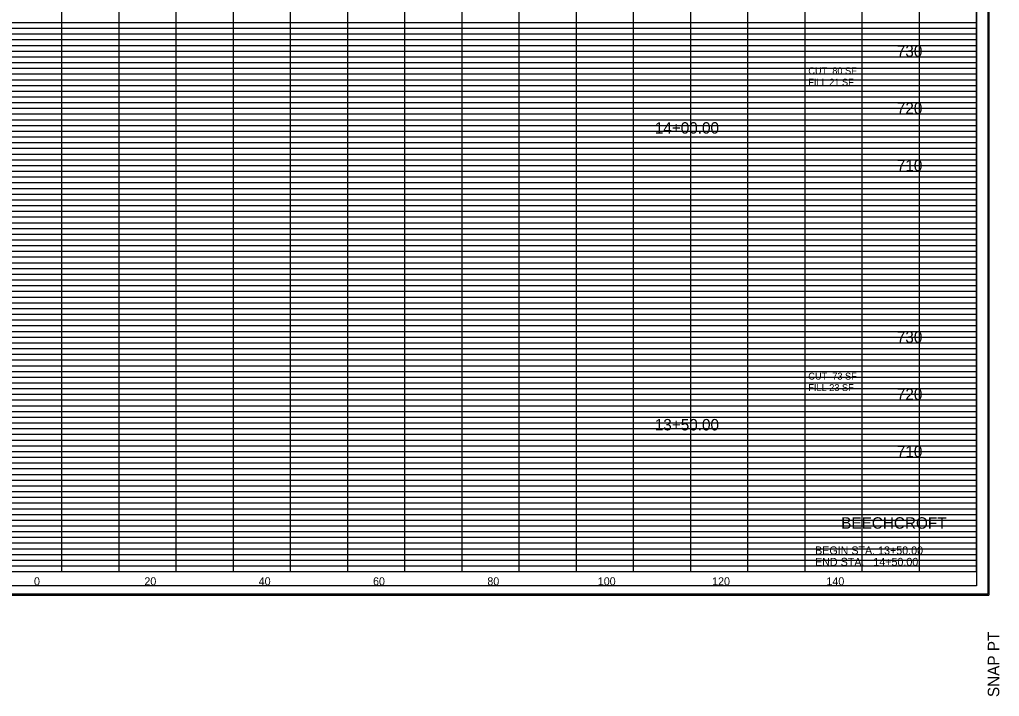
# Model space of a CAD drawing. Extents: x -200 to 1704, y -325 to 2307.
# Drawn here: x 1152.6 to 1324, y 1248.2 to 1366.5 of the extents above; entities that cross this region are included whole.
import ezdxf

# ---------------------------------------------------------------- set-up
doc = ezdxf.new("R2010")
doc.units = 0
for name, color, linetype in [('DESIGN - SHEET - Corner Text', 7, 'Continuous'), ('DESIGN - SHEET - Light Grid', 7, 'Continuous'), ('DESIGN - SHEET - Linework', 7, 'Continuous'), ('DESIGN - SHEET - Plot Shape', 7, 'Continuous'), ('DESIGN - TYPICAL - Text', 7, 'Continuous')]:
    doc.layers.add(name, color=color, linetype=linetype)

msp = doc.modelspace()

# ---------------------------------------------------------------- linework, layer by layer
at = {"layer": 'DESIGN - SHEET - Light Grid'}
for p, q in [((1080, 1366), (1160, 1366)), ((1080, 1365), (1160, 1365)), ((1160, 1366), (1240, 1366)), ((1160, 1365), (1240, 1365)), ((1240, 1366), (1320, 1366)), ((1240, 1365), (1320, 1365)), ((1080, 1364), (1160, 1364)), ((1080, 1363), (1160, 1363)), ((1160, 1364), (1240, 1364)), ((1160, 1363), (1240, 1363)), ((1240, 1364), (1320, 1364)), ((1240, 1363), (1320, 1363)), ((1080, 1362), (1160, 1362)), ((1080, 1361), (1160, 1361)), ((1160, 1362), (1240, 1362)), ((1160, 1361), (1240, 1361)), ((1240, 1362), (1320, 1362)), ((1240, 1361), (1320, 1361)), ((1080, 1359), (1160, 1359)), ((1080, 1358), (1160, 1358)), ((1160, 1359), (1240, 1359)), ((1160, 1358), (1240, 1358)), ((1240, 1359), (1320, 1359)), ((1240, 1358), (1320, 1358)), ((1080, 1357), (1160, 1357)), ((1080, 1356), (1160, 1356)), ((1160, 1357), (1240, 1357)), ((1160, 1356), (1240, 1356)), ((1240, 1357), (1320, 1357)), ((1240, 1356), (1320, 1356)), ((1080, 1355), (1160, 1355)), ((1160, 1355), (1240, 1355)), ((1240, 1355), (1320, 1355)), ((1080, 1354), (1160, 1354)), ((1080, 1353), (1160, 1353)), ((1160, 1354), (1240, 1354)), ((1160, 1353), (1240, 1353)), ((1240, 1354), (1320, 1354)), ((1240, 1353), (1320, 1353)), ((1080, 1352), (1160, 1352)), ((1080, 1351), (1160, 1351)), ((1160, 1352), (1240, 1352)), ((1160, 1351), (1240, 1351)), ((1240, 1352), (1320, 1352)), ((1240, 1351), (1320, 1351)), ((1080, 1349), (1160, 1349)), ((1160, 1349), (1240, 1349)), ((1240, 1349), (1320, 1349)), ((1080, 1348), (1160, 1348)), ((1160, 1348), (1240, 1348)), ((1240, 1348), (1320, 1348)), ((1080, 1347), (1160, 1347)), ((1080, 1346), (1160, 1346)), ((1160, 1347), (1240, 1347)), ((1160, 1346), (1240, 1346)), ((1240, 1347), (1320, 1347)), ((1240, 1346), (1320, 1346)), ((1080, 1345), (1160, 1345)), ((1080, 1344), (1160, 1344)), ((1160, 1345), (1240, 1345)), ((1160, 1344), (1240, 1344)), ((1240, 1345), (1320, 1345)), ((1240, 1344), (1320, 1344)), ((1080, 1343), (1160, 1343)), ((1160, 1343), (1240, 1343)), ((1240, 1343), (1320, 1343)), ((1080, 1342), (1160, 1342)), ((1080, 1341), (1160, 1341)), ((1160, 1342), (1240, 1342)), ((1160, 1341), (1240, 1341)), ((1240, 1342), (1320, 1342)), ((1240, 1341), (1320, 1341)), ((1080, 1339), (1160, 1339)), ((1160, 1339), (1240, 1339)), ((1240, 1339), (1320, 1339)), ((1080, 1338), (1160, 1338)), ((1080, 1337), (1160, 1337)), ((1160, 1338), (1240, 1338)), ((1160, 1337), (1240, 1337)), ((1240, 1338), (1320, 1338)), ((1240, 1337), (1320, 1337)), ((1080, 1336), (1160, 1336)), ((1160, 1336), (1240, 1336)), ((1240, 1336), (1320, 1336)), ((1080, 1335), (1160, 1335)), ((1080, 1334), (1160, 1334)), ((1160, 1335), (1240, 1335)), ((1160, 1334), (1240, 1334)), ((1240, 1335), (1320, 1335)), ((1240, 1334), (1320, 1334)), ((1080, 1333), (1160, 1333)), ((1080, 1332), (1160, 1332)), ((1160, 1333), (1240, 1333)), ((1160, 1332), (1240, 1332)), ((1240, 1333), (1320, 1333)), ((1240, 1332), (1320, 1332)), ((1080, 1331), (1160, 1331)), ((1160, 1331), (1240, 1331)), ((1240, 1331), (1320, 1331)), ((1080, 1329), (1160, 1329)), ((1160, 1329), (1240, 1329)), ((1240, 1329), (1320, 1329)), ((1080, 1328), (1160, 1328)), ((1080, 1327), (1160, 1327)), ((1160, 1328), (1240, 1328)), ((1160, 1327), (1240, 1327)), ((1240, 1328), (1320, 1328)), ((1240, 1327), (1320, 1327)), ((1080, 1326), (1160, 1326)), ((1080, 1325), (1160, 1325)), ((1160, 1326), (1240, 1326)), ((1160, 1325), (1240, 1325)), ((1240, 1326), (1320, 1326)), ((1240, 1325), (1320, 1325)), ((1080, 1324), (1160, 1324)), ((1160, 1324), (1240, 1324)), ((1240, 1324), (1320, 1324)), ((1080, 1323), (1160, 1323)), ((1080, 1322), (1160, 1322)), ((1160, 1323), (1240, 1323)), ((1160, 1322), (1240, 1322)), ((1240, 1323), (1320, 1323)), ((1240, 1322), (1320, 1322)), ((1080, 1321), (1160, 1321)), ((1160, 1321), (1240, 1321)), ((1240, 1321), (1320, 1321)), ((1080, 1319), (1160, 1319)), ((1160, 1319), (1240, 1319)), ((1240, 1319), (1320, 1319)), ((1080, 1318), (1160, 1318)), ((1080, 1317), (1160, 1317)), ((1160, 1318), (1240, 1318)), ((1160, 1317), (1240, 1317)), ((1240, 1318), (1320, 1318)), ((1240, 1317), (1320, 1317)), ((1080, 1316), (1160, 1316)), ((1080, 1315), (1160, 1315)), ((1160, 1316), (1240, 1316)), ((1160, 1315), (1240, 1315)), ((1240, 1316), (1320, 1316)), ((1240, 1315), (1320, 1315)), ((1080, 1314), (1160, 1314)), ((1080, 1313), (1160, 1313)), ((1160, 1314), (1240, 1314)), ((1160, 1313), (1240, 1313)), ((1240, 1314), (1320, 1314)), ((1240, 1313), (1320, 1313)), ((1080, 1312), (1160, 1312)), ((1160, 1312), (1240, 1312)), ((1240, 1312), (1320, 1312)), ((1080, 1311), (1160, 1311)), ((1160, 1311), (1240, 1311)), ((1240, 1311), (1320, 1311)), ((1080, 1309), (1160, 1309)), ((1080, 1308), (1160, 1308)), ((1160, 1309), (1240, 1309)), ((1160, 1308), (1240, 1308)), ((1240, 1309), (1320, 1309)), ((1240, 1308), (1320, 1308)), ((1080, 1307), (1160, 1307)), ((1160, 1307), (1240, 1307)), ((1240, 1307), (1320, 1307)), ((1080, 1306), (1160, 1306)), ((1080, 1305), (1160, 1305)), ((1160, 1306), (1240, 1306)), ((1160, 1305), (1240, 1305)), ((1240, 1306), (1320, 1306)), ((1240, 1305), (1320, 1305)), ((1080, 1304), (1160, 1304)), ((1080, 1303), (1160, 1303)), ((1160, 1304), (1240, 1304)), ((1160, 1303), (1240, 1303)), ((1240, 1304), (1320, 1304)), ((1240, 1303), (1320, 1303)), ((1080, 1302), (1160, 1302)), ((1080, 1301), (1160, 1301)), ((1160, 1302), (1240, 1302)), ((1160, 1301), (1240, 1301)), ((1240, 1302), (1320, 1302)), ((1240, 1301), (1320, 1301)), ((1080, 1299), (1160, 1299)), ((1080, 1298), (1160, 1298)), ((1160, 1299), (1240, 1299)), ((1160, 1298), (1240, 1298)), ((1240, 1299), (1320, 1299)), ((1240, 1298), (1320, 1298)), ((1080, 1297), (1160, 1297)), ((1080, 1296), (1160, 1296)), ((1160, 1297), (1240, 1297)), ((1160, 1296), (1240, 1296)), ((1240, 1297), (1320, 1297)), ((1240, 1296), (1320, 1296)), ((1080, 1295), (1160, 1295)), ((1160, 1295), (1240, 1295)), ((1240, 1295), (1320, 1295)), ((1080, 1294), (1160, 1294)), ((1080, 1293), (1160, 1293)), ((1160, 1294), (1240, 1294)), ((1160, 1293), (1240, 1293)), ((1240, 1294), (1320, 1294)), ((1240, 1293), (1320, 1293)), ((1080, 1292), (1160, 1292)), ((1080, 1291), (1160, 1291)), ((1160, 1292), (1240, 1292)), ((1160, 1291), (1240, 1291)), ((1240, 1292), (1320, 1292)), ((1240, 1291), (1320, 1291)), ((1080, 1289), (1160, 1289)), ((1160, 1289), (1240, 1289)), ((1240, 1289), (1320, 1289)), ((1080, 1288), (1160, 1288)), ((1160, 1288), (1240, 1288)), ((1240, 1288), (1320, 1288)), ((1080, 1287), (1160, 1287)), ((1080, 1286), (1160, 1286)), ((1160, 1287), (1240, 1287)), ((1160, 1286), (1240, 1286)), ((1240, 1287), (1320, 1287)), ((1240, 1286), (1320, 1286)), ((1080, 1285), (1160, 1285)), ((1080, 1284), (1160, 1284)), ((1160, 1285), (1240, 1285)), ((1160, 1284), (1240, 1284)), ((1240, 1285), (1320, 1285)), ((1240, 1284), (1320, 1284)), ((1080, 1283), (1160, 1283)), ((1160, 1283), (1240, 1283)), ((1240, 1283), (1320, 1283)), ((1080, 1282), (1160, 1282)), ((1080, 1281), (1160, 1281)), ((1160, 1282), (1240, 1282)), ((1160, 1281), (1240, 1281)), ((1240, 1282), (1320, 1282)), ((1240, 1281), (1320, 1281)), ((1080, 1279), (1160, 1279)), ((1160, 1279), (1240, 1279)), ((1240, 1279), (1320, 1279)), ((1080, 1278), (1160, 1278)), ((1080, 1277), (1160, 1277)), ((1160, 1278), (1240, 1278)), ((1160, 1277), (1240, 1277)), ((1240, 1278), (1320, 1278)), ((1240, 1277), (1320, 1277)), ((1080, 1276), (1160, 1276)), ((1160, 1276), (1240, 1276)), ((1240, 1276), (1320, 1276)), ((1080, 1275), (1160, 1275)), ((1080, 1274), (1160, 1274)), ((1160, 1275), (1240, 1275)), ((1160, 1274), (1240, 1274)), ((1240, 1275), (1320, 1275)), ((1240, 1274), (1320, 1274)), ((1080, 1273), (1160, 1273)), ((1080, 1272), (1160, 1272)), ((1160, 1273), (1240, 1273)), ((1160, 1272), (1240, 1272)), ((1240, 1273), (1320, 1273)), ((1240, 1272), (1320, 1272)), ((1080, 1271), (1160, 1271)), ((1160, 1271), (1240, 1271)), ((1240, 1271), (1320, 1271))]:
    msp.add_line(p, q, dxfattribs=at)
at = {"layer": 'DESIGN - SHEET - Linework'}
for p, q in [((1322.17, 1484.14), (1322.17, 1265.86)), ((1160, 1270), (1160, 1480)), ((1170, 1270), (1170, 1480)), ((1180, 1270), (1180, 1480)), ((1190, 1270), (1190, 1480)), ((1200, 1270), (1200, 1480)), ((1210, 1270), (1210, 1480)), ((1220, 1270), (1220, 1480)), ((1230, 1270), (1230, 1480)), ((1240, 1270), (1240, 1480)), ((1250, 1270), (1250, 1480)), ((1260, 1270), (1260, 1480)), ((1270, 1270), (1270, 1480)), ((1280, 1270), (1280, 1470)), ((1290, 1270), (1290, 1470)), ((1300, 1270), (1300, 1470)), ((1310, 1270), (1310, 1470)), ((1000, 1360), (1320, 1360)), ((1000, 1350), (1320, 1350)), ((1000, 1340), (1320, 1340)), ((1000, 1330), (1320, 1330)), ((1000, 1320), (1320, 1320)), ((1000, 1310), (1320, 1310)), ((1000, 1300), (1320, 1300)), ((1000, 1290), (1320, 1290)), ((1000, 1280), (1320, 1280)), ((981.77, 1265.86), (1322.17, 1265.86))]:
    msp.add_line(p, q, dxfattribs=at)
msp.add_lwpolyline([(1000, 1480), (1000, 1270), (1320, 1270), (1320, 1480), (1000, 1480)], dxfattribs=at)
at = {"layer": 'DESIGN - SHEET - Plot Shape'}
for points in [[(981.97, 1483.94), (1321.97, 1483.94), (1321.97, 1266.06), (981.97, 1266.06)], [(991.5, 1480), (1320, 1480), (1320, 1267.5), (991.5, 1267.5)]]:
    msp.add_lwpolyline(points, close=True, dxfattribs=at)

# ---------------------------------------------------------------- texts
at = {"layer": 'DESIGN - SHEET - Corner Text'}
for s, height, p in [('BEECHCROFT ', 2, (1296.33, 1277.5)), ('BEGIN STA. 13+50.00', 1.4, (1291.75, 1273)), ('END STA.   14+50.00', 1.4, (1291.75, 1271))]:
    msp.add_text(s, height=height, dxfattribs=at).set_placement(p)
msp.add_text('SNAP PT  ', height=2, rotation=90, dxfattribs=at).set_placement((1323.97, 1248.06))
at = {"layer": 'DESIGN - TYPICAL - Text'}
for s, height, p in [('     730     ', 2, (1302.34, 1360)), ('CUT  80 SF', 1.2, (1290.57, 1356.96)), ('FILL 21 SF', 1.2, (1290.57, 1354.96)), ('     720     ', 2, (1302.34, 1350)), ('     14+00.00     ', 2, (1260, 1346.57)), ('     710     ', 2, (1302.34, 1340)), ('     730     ', 2, (1302.34, 1310)), ('CUT  73 SF', 1.2, (1290.57, 1303.57)), ('FILL 23 SF', 1.2, (1290.57, 1301.57)), ('     720     ', 2, (1302.34, 1300)), ('     13+50.00     ', 2, (1260, 1294.68)), ('     710     ', 2, (1302.34, 1290)), ('     0     ', 1.4, (1152.51, 1267.6)), ('     20     ', 1.4, (1171.82, 1267.6)), ('     40     ', 1.4, (1191.82, 1267.6)), ('     60     ', 1.4, (1211.82, 1267.6)), ('     80     ', 1.4, (1231.82, 1267.6)), ('     100     ', 1.4, (1251.14, 1267.6)), ('     120     ', 1.4, (1271.14, 1267.6)), ('     140     ', 1.4, (1291.14, 1267.6))]:
    msp.add_text(s, height=height, dxfattribs=at).set_placement(p)

doc.saveas('drawing.dxf')
